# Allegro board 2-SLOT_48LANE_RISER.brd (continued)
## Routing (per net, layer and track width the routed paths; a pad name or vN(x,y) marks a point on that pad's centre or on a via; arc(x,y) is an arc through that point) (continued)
GND_L:
  vias: v2(-18.72,363.74) v2(-18.72,362.74) v2(-18.72,361.74) v2(-18.72,360.74) v2(-18.72,359.74) v2(-18.72,358.74) v2(-18.72,357.74) v2(-18.72,356.74) v2(-18.72,355.74) v2(-18.72,354.74) v2(-18.72,353.74) v2(-18.72,352.74) v2(-18.72,351.74) v2(-18.72,350.74) v2(-18.72,349.74) v2(-18.72,348.74) v2(-18.72,347.74) v2(-18.72,346.74) v2(-18.72,345.74) v2(-18.72,344.74) v2(-18.72,343.74) v2(-18.72,342.74) v2(-18.72,341.74) v2(-18.72,340.74) v2(-18.72,339.74) v2(-18.72,338.74) v2(-18.72,337.74) v2(-18.72,336.74) v2(-18.72,335.74) v2(-18.72,334.74) v2(-18.72,333.74) v2(-18.72,332.74) v2(-18.72,331.74) v2(-18.72,330.74) v2(-18.72,329.74) v2(-18.72,328.74) v2(-18.72,327.74) v2(-18.72,326.74) v2(-18.72,325.74) v2(-18.72,324.74) v2(-18.72,323.74) v2(-18.72,322.74) v2(-18.72,321.74) v2(-18.72,320.74) v2(-18.72,319.74) v2(-18.72,318.74) v2(-18.72,317.74) v2(-18.72,316.74) v2(-18.72,315.74) v2(-18.72,314.74) v2(-18.72,313.74) v2(-18.72,312.74) v2(-18.72,311.74) v2(-18.72,310.74) v2(-18.72,309.74) v2(-18.72,308.74) v2(-18.72,307.74) v2(-18.72,306.74) v2(-18.72,305.74) v2(-18.72,304.74) v2(-18.72,303.74) v2(-18.72,302.74) v2(-18.72,301.74) v2(-18.72,300.74) v2(-18.72,299.74) v2(-18.72,298.74) v2(-18.72,297.74) v2(-18.72,296.74) v2(-18.72,295.74) v2(-18.72,294.74) v2(-18.72,293.74) v2(-18.72,292.74) v2(-18.72,291.74) v2(-18.72,290.74) v2(-18.72,289.74) v2(-18.72,288.74) v2(-18.72,287.74) v2(-18.72,286.74) v2(-18.72,285.74) v2(-18.72,284.74) v2(-18.72,283.74) v2(-18.72,282.74) v2(-18.72,281.74) v2(-18.72,280.74) v2(-18.72,279.74) v2(-18.72,278.74) v2(-18.72,277.74) v2(-18.72,276.74) v2(-18.72,275.74) v2(-18.72,274.74) v2(-18.72,273.74) v2(-18.72,272.74) v2(-18.72,271.74) v2(-18.72,270.74) v2(-18.72,269.74) v2(-18.72,268.74) v2(-18.72,267.74) v2(-18.72,266.74) v2(-18.72,265.74) v2(-18.72,264.74) v2(-18.72,263.74) v2(-18.72,262.74) v2(-18.72,261.74) v2(-18.72,260.74) v2(-18.72,259.74) v2(-18.72,258.74) v2(-18.72,257.74) v2(-18.72,256.74) v2(-18.72,255.74) v2(-18.72,254.74) v2(-18.72,253.74) v2(-18.72,252.74) v2(-18.72,251.74) v2(-18.72,250.74) v2(-18.72,249.74) v2(-18.72,248.74) v2(-18.72,247.74) v2(-18.72,246.74) v2(-18.72,245.74) v2(-18.72,244.74) v2(-18.72,243.74) v2(-18.72,242.74) v2(-18.72,241.74) v2(-18.72,240.74) v2(-18.72,239.74) v2(-18.72,238.74) v2(-18.72,237.74) v2(-18.72,236.74) v2(-18.72,235.74) v2(-18.72,234.74) v2(-18.72,233.74) v2(-18.72,232.74) v2(-18.72,231.74) v2(-18.72,230.74) v2(-18.72,229.74) v2(-18.72,228.74) v2(-18.72,227.74) v2(-18.72,226.74) v2(-18.72,225.74) v2(-18.72,224.74) v2(-18.72,223.74) v2(-18.72,222.74) v2(-18.72,221.74) v2(-18.72,220.74) v2(-18.72,219.74) v2(-18.72,218.74) v2(-18.72,217.74) v2(-18.72,216.74) v2(-18.72,215.74) v2(-18.72,214.74) v2(-18.72,213.74) v2(-18.72,212.74) v2(-18.72,211.74) v2(-18.72,210.74) v2(-18.72,209.74) v2(-18.72,208.74) v2(-18.72,207.74) v2(-18.72,206.74) v2(-18.72,205.74) v2(-18.72,204.74) v2(-18.72,203.74) v2(-18.72,202.74) v2(-18.72,201.74) v2(-18.72,200.74) v2(-18.72,199.74) v2(-18.72,198.74) v2(-18.72,197.74) v2(-18.72,196.74) v2(-18.72,195.74) v2(-18.72,194.74) v2(-18.72,193.74) v2(-18.72,192.74) v2(-18.72,191.74) v2(-18.72,190.74) v2(-18.72,189.74) v2(-18.72,188.74) v2(-18.72,187.74) v2(-18.72,186.74) v2(-18.72,185.74) v2(-18.72,184.74) v2(-18.72,183.74) v2(-18.72,182.74) v2(-18.72,181.74) v2(-18.72,180.74) v2(-18.72,179.74) v2(-18.72,178.74) v2(-18.72,177.74) v2(-18.72,176.74) v2(-18.72,175.74) v2(-18.72,174.74) v2(-18.72,173.74) v2(-18.72,172.74) v2(-18.72,171.74) v2(-18.72,170.74) v2(-18.72,169.74) v2(-18.72,168.74) v2(-18.72,167.74) v2(-18.72,166.74) v2(-18.72,165.74) v2(-18.72,164.74) v2(-18.72,163.74) v2(-18.72,162.74) v2(-18.72,161.74) v2(-18.72,160.74) v2(-18.72,159.74) v2(-18.72,158.74) v2(-18.72,157.74) v2(-18.72,156.74) v2(-18.72,155.74) v2(-18.72,154.74) v2(-18.72,153.74) v2(-18.72,152.74) v2(-18.72,151.74) v2(-18.72,150.74) v2(-18.72,149.74) v2(-18.72,148.74) v2(-18.72,147.74) v2(-18.72,146.74) v2(-18.72,145.74) v2(-18.72,144.74) v2(-18.72,143.74) v2(-18.72,142.74) v2(-18.72,141.74) v2(-18.72,140.74) v2(-18.72,139.74) v2(-18.72,138.74) v2(-18.72,137.74) v2(-18.72,136.74) v2(-18.72,135.74) v2(-18.72,134.74) v2(-18.72,133.74) v2(-18.72,132.74) v2(-18.72,131.74) v2(-18.72,130.74) v2(-18.72,129.74) v2(-18.72,128.74) v2(-18.72,127.74) v2(-18.72,126.74) v2(-18.72,125.74) v2(-18.72,124.74) v2(-18.72,123.74) v2(-18.72,122.74) v2(-18.72,121.74) v2(-18.72,120.74) v2(-18.72,119.74) v2(-18.72,118.74) v2(-18.72,117.74) v2(-18.72,116.74) v2(-18.72,115.74) v2(-18.72,114.74) v2(-18.72,113.74) v2(-18.72,112.74) v2(-18.72,111.74) v2(-18.72,110.74) v2(-18.72,109.74) v2(-18.72,108.74) v2(-18.72,107.74) v2(-18.72,106.74) v2(-18.72,105.74) v2(-18.72,104.74) v2(-18.72,103.74) v2(-18.72,102.74) v2(-18.72,101.74) v2(-18.72,100.74) v2(-18.72,99.74) v2(-18.72,98.74) v2(-18.72,97.74) v2(-18.72,96.74) v2(-18.72,95.74) v2(-18.72,94.74) v2(-18.72,93.74) v2(-18.72,92.74) v2(-18.72,91.74) v2(-18.72,90.74) v2(-18.72,89.74) v2(-18.72,88.74) v2(-18.72,87.74) v2(-18.72,86.74) v2(-18.72,85.74) v2(-18.72,84.74) v2(-18.72,83.74) v2(-18.72,82.74) v2(-18.72,81.74) v2(-18.72,80.74) v2(-18.72,79.74) v2(-18.72,78.74) v2(-18.72,77.74) v2(-18.72,76.74) v2(-18.72,75.74) v2(-18.72,74.74) v2(-18.72,73.74) v2(-18.72,72.74) v2(-18.72,71.74) v2(-18.72,70.74) v2(-18.72,69.74) v2(-18.72,68.74) v2(-18.72,67.74) v2(-18.72,66.74) v2(-18.72,65.74) v2(-18.72,64.74) v2(-18.72,63.74) v2(-18.72,62.74) v2(-18.72,61.74) v2(-18.72,60.74) v2(-18.72,59.74) v2(-18.72,58.74) v2(-18.72,57.74) v2(-18.72,56.74) v2(-18.72,55.74) v2(-18.72,54.74) v2(-18.72,53.74) v2(-18.72,52.74) v2(-18.72,51.74) v2(-18.72,50.74) v2(-18.72,49.74) v2(-18.72,48.74) v2(-18.72,47.74) v2(-18.72,46.74) v2(-18.72,45.74) v2(-18.72,44.74) v2(-18.72,43.74) v2(-18.72,42.74) v2(-18.72,41.74) v2(-18.72,40.74) v2(-18.72,39.74) v2(-18.72,38.74) v2(-18.72,37.74) v2(-18.72,36.74) v2(-18.72,35.74) v2(-18.72,34.74) v2(-18.72,33.74) v2(-18.72,32.74) v2(-18.72,31.74) v2(-18.72,30.74) v2(-18.72,29.74) v2(-18.72,28.74) v2(-18.72,27.74) v2(-18.72,26.74) v2(-18.72,25.74) v2(-18.72,24.74) v2(-18.72,23.74) v2(-18.72,22.74) v2(-18.72,21.74) v2(-18.72,20.74) v2(-18.72,19.74) v2(-18.72,18.74) v2(-18.72,17.74) v2(-18.72,16.74) v2(-18.72,15.74) v2(-18.72,14.74) v2(-18.72,13.74) v2(-18.72,12.74) v2(-18.72,11.74) v2(-18.72,10.74) v2(-18.72,9.74) v2(-18.72,8.74) v2(-18.72,7.74) v2(-18.72,6.74) v2(-18.72,5.74) v2(-18.72,4.74) v2(-18.72,3.74) v2(-18.72,2.74) v2(-18.72,1.74) v2(-18.72,0.74) v2(-18.72,-0.26) v2(-18.72,-1.26) v2(-18.72,-2.26) v2(-18.72,-3.26) v2(-18.72,-4.26) v2(-18.72,-5.26) v2(-18.72,-6.26) v2(-18.72,-7.26) v2(-18.72,-8.26) v2(-17.1,65.8) v2(-17.1,64.8) v2(-17.1,63.8) v2(-17.1,62.8) v2(-17.1,61.8) v2(-17.1,60.8) v2(-17.1,59.8) v2(-17.1,58.8) v2(-17.1,57.8) v2(-17.1,56.8) v2(-17.1,55.8) v2(-17.1,54.8) v2(-17.1,53.8) v2(-17.1,52.8) v2(-17.1,51.8) v2(-17.1,50.8) v2(-16.97,299.48) v2(-16.97,298.48) v2(-16.97,297.48) v2(-16.97,296.48) v2(-16.97,295.48) v2(-16.97,294.48) v2(-16.97,293.48) v2(-16.97,292.48) v2(-16.97,291.48) v2(-16.97,290.48) v2(-16.97,289.48) v2(-16.97,288.48) v2(-16.97,287.48) v2(-16.97,286.48) v2(-16.97,285.48) v2(-16.97,284.48) v2(-16.97,237.38) v2(-16.97,236.38) v2(-16.97,235.38) v2(-16.97,234.38) v2(-16.97,233.38) v2(-16.97,232.38) v2(-16.97,231.38) v2(-16.97,230.38) v2(-16.97,229.38) v2(-16.97,228.38) v2(-16.97,227.38) v2(-16.97,4.21) v2(-16.97,3.21) v2(-16.97,2.21) v2(-16.97,1.21) v2(-16.97,0.21) v2(-16.97,-0.79) v2(-16.97,-1.79) v2(-16.97,-2.79) v2(-16.97,-3.79) v2(-16.97,-4.79) v2(-16.97,-5.79) v2(-16.97,-6.79) v2(-16.97,-7.79) v2(-16.85,180.36) v2(-16.85,179.36) v2(-16.85,178.36) v2(-16.85,177.36) v2(-16.85,176.36) v2(-16.85,175.36) v2(-16.85,174.36) v2(-16.85,173.36) v2(-16.85,172.36) v2(-16.85,171.36) v2(-16.85,170.36) v2(-16.85,122.95) v2(-16.85,121.95) v2(-16.85,120.95) v2(-16.85,119.95) v2(-16.85,118.95) v2(-16.85,117.95) v2(-16.85,116.95) v2(-16.85,115.95) v2(-16.85,114.95) v2(-16.85,113.95) v2(-16.85,112.95) v2(-16.72,363.74) v2(-16.72,362.74) v2(-16.72,361.74) v2(-16.72,360.74) v2(-16.72,359.74) v2(-16.72,358.74) v2(-16.72,357.74) v2(-16.72,356.74) v2(-16.72,355.74) v2(-16.72,354.74) v2(-16.72,353.74) v2(-16.72,352.74) v2(-16.72,351.74) v2(-16.72,350.74) v2(-16.72,349.74) v2(-16.72,348.74) v2(-16.72,347.74) v2(-16.72,346.74) v2(-15.1,65.8) v2(-15.1,64.8) v2(-15.1,63.8) v2(-15.1,62.8) v2(-15.1,61.8) v2(-15.1,60.8) v2(-15.1,59.8) v2(-15.1,58.8) v2(-15.1,57.8) v2(-15.1,56.8) v2(-15.1,55.8) v2(-15.1,54.8) v2(-15.1,53.8) v2(-15.1,52.8) v2(-15.1,51.8) v2(-15.1,50.8) v2(-14.97,299.48) v2(-14.97,298.48) v2(-14.97,297.48) v2(-14.97,296.48) v2(-14.97,295.48) v2(-14.97,294.48) v2(-14.97,293.48) v2(-14.97,292.48) v2(-14.97,291.48) v2(-14.97,290.48) v2(-14.97,289.48) v2(-14.97,288.48) v2(-14.97,287.48) v2(-14.97,286.48) v2(-14.97,285.48) v2(-14.97,284.48) v2(-14.97,237.38) v2(-14.97,236.38) v2(-14.97,235.38) v2(-14.97,234.38) v2(-14.97,233.38) v2(-14.97,232.38) v2(-14.97,231.38) v2(-14.97,230.38) v2(-14.97,229.38) v2(-14.97,228.38) v2(-14.97,227.38) v2(-14.97,4.21) v2(-14.97,3.21) v2(-14.97,2.21) v2(-14.97,1.21) v2(-14.97,0.21) v2(-14.97,-0.79) v2(-14.97,-1.79) v2(-14.97,-2.79) v2(-14.97,-3.79) v2(-14.97,-4.79) v2(-14.97,-5.79) v2(-14.97,-6.79) v2(-14.97,-7.79) v2(-14.85,180.36) v2(-14.85,179.36) v2(-14.85,178.36) v2(-14.85,177.36) v2(-14.85,176.36) v2(-14.85,175.36) v2(-14.85,174.36) v2(-14.85,173.36) v2(-14.85,172.36) v2(-14.85,171.36) v2(-14.85,170.36) v2(-14.85,122.95) v2(-14.85,121.95) v2(-14.85,120.95) v2(-14.85,119.95) v2(-14.85,118.95) v2(-14.85,117.95) v2(-14.85,116.95) v2(-14.85,115.95) v2(-14.85,114.95) v2(-14.85,113.95) v2(-14.85,112.95) v2(-14.72,363.74) v2(-14.72,362.74) v2(-14.72,361.74) v2(-14.72,360.74) v2(-14.72,359.74) v2(-14.72,358.74) v2(-14.72,357.74) v2(-14.72,356.74) v2(-14.72,355.74) v2(-14.72,354.74) v2(-14.72,353.74) v2(-14.72,352.74) v2(-14.72,351.74) v2(-14.72,350.74) v2(-14.72,349.74) v2(-14.72,348.74) v2(-14.72,347.74) v2(-14.72,346.74) v2(-13.1,65.8) v2(-13.1,64.8) v2(-13.1,63.8) v2(-13.1,62.8) v2(-13.1,61.8) v2(-13.1,60.8) v2(-13.1,59.8) v2(-13.1,58.8) v2(-13.1,57.8) v2(-13.1,56.8) v2(-13.1,55.8) v2(-13.1,54.8) v2(-13.1,53.8) v2(-13.1,52.8) v2(-13.1,51.8) v2(-13.1,50.8) v2(-12.97,299.48) v2(-12.97,298.48) v2(-12.97,297.48) v2(-12.97,296.48) v2(-12.97,295.48) v2(-12.97,294.48) v2(-12.97,293.48) v2(-12.97,292.48) v2(-12.97,291.48) v2(-12.97,290.48) v2(-12.97,289.48) v2(-12.97,288.48) v2(-12.97,287.48) v2(-12.97,286.48) v2(-12.97,285.48) v2(-12.97,284.48) v2(-12.97,237.38) v2(-12.97,236.38) v2(-12.97,235.38) v2(-12.97,234.38) v2(-12.97,233.38) v2(-12.97,232.38) v2(-12.97,231.38) v2(-12.97,230.38) v2(-12.97,229.38) v2(-12.97,228.38) v2(-12.97,227.38) v2(-12.97,4.21) v2(-12.97,3.21) v2(-12.97,2.21) v2(-12.97,1.21) v2(-12.97,0.21) v2(-12.97,-0.79) v2(-12.97,-1.79) v2(-12.97,-2.79) v2(-12.97,-3.79) v2(-12.97,-4.79) v2(-12.97,-5.79) v2(-12.97,-6.79) v2(-12.97,-7.79) v2(-12.85,180.36) v2(-12.85,179.36) v2(-12.85,178.36) v2(-12.85,177.36) v2(-12.85,176.36) v2(-12.85,175.36) v2(-12.85,174.36) v2(-12.85,173.36) v2(-12.85,172.36) v2(-12.85,171.36) v2(-12.85,170.36) v2(-12.85,122.95) v2(-12.85,121.95) v2(-12.85,120.95) v2(-12.85,119.95) v2(-12.85,118.95) v2(-12.85,117.95) v2(-12.85,116.95) v2(-12.85,115.95) v2(-12.85,114.95) v2(-12.85,113.95) v2(-12.85,112.95) v2(-12.72,363.74) v2(-12.72,362.74) v2(-12.72,361.74) v2(-12.72,360.74) v2(-12.72,359.74) v2(-12.72,358.74) v2(-12.72,357.74) v2(-12.72,356.74) v2(-12.72,355.74) v2(-12.72,354.74) v2(-12.72,353.74) v2(-12.72,352.74) v2(-12.72,351.74) v2(-12.72,350.74) v2(-12.72,349.74) v2(-12.72,348.74) v2(-12.72,347.74) v2(-12.72,346.74) v2(-11.1,65.8) v2(-11.1,64.8) v2(-11.1,63.8) v2(-11.1,62.8) v2(-11.1,61.8) v2(-11.1,60.8) v2(-11.1,59.8) v2(-11.1,58.8) v2(-11.1,57.8) v2(-11.1,56.8) v2(-11.1,55.8) v2(-11.1,54.8) v2(-11.1,53.8) v2(-11.1,52.8) v2(-11.1,51.8) v2(-11.1,50.8) v2(-10.97,299.48) v2(-10.97,298.48) v2(-10.97,297.48) v2(-10.97,296.48) v2(-10.97,295.48) v2(-10.97,294.48) v2(-10.97,293.48) v2(-10.97,292.48) v2(-10.97,291.48) v2(-10.97,290.48) v2(-10.97,289.48) v2(-10.97,288.48) v2(-10.97,287.48) v2(-10.97,286.48) v2(-10.97,285.48) v2(-10.97,284.48) v2(-10.97,237.38) v2(-10.97,236.38) v2(-10.97,235.38) v2(-10.97,234.38) v2(-10.97,233.38) v2(-10.97,232.38) v2(-10.97,231.38) v2(-10.97,230.38) v2(-10.97,229.38) v2(-10.97,228.38) v2(-10.97,227.38) v2(-10.97,4.21) v2(-10.97,3.21) v2(-10.97,2.21) v2(-10.97,1.21) v2(-10.97,0.21) v2(-10.97,-0.79) v2(-10.97,-1.79) v2(-10.97,-2.79) v2(-10.97,-3.79) v2(-10.97,-4.79) v2(-10.97,-5.79) v2(-10.97,-6.79) v2(-10.97,-7.79) v2(-10.85,180.36) v2(-10.85,179.36) v2(-10.85,178.36) v2(-10.85,177.36) v2(-10.85,176.36) v2(-10.85,175.36) v2(-10.85,174.36) v2(-10.85,173.36) v2(-10.85,172.36) v2(-10.85,171.36) v2(-10.85,170.36) v2(-10.85,122.95) v2(-10.85,121.95) v2(-10.85,120.95) v2(-10.85,119.95) v2(-10.85,118.95) v2(-10.85,117.95) v2(-10.85,116.95) v2(-10.85,115.95) v2(-10.85,114.95) v2(-10.85,113.95) v2(-10.85,112.95) v2(-10.72,363.74) v2(-10.72,362.74) v2(-10.72,361.74) v2(-10.72,360.74) v2(-10.72,359.74) v2(-10.72,358.74) v2(-10.72,357.74) v2(-10.72,356.74) v2(-10.72,355.74) v2(-10.72,354.74) v2(-10.72,353.74) v2(-10.72,352.74) v2(-10.72,351.74) v2(-10.72,350.74) v2(-10.72,349.74) v2(-10.72,348.74) v2(-10.72,347.74) v2(-10.72,346.74) v2(-9.1,65.8) v2(-9.1,64.8) v2(-9.1,63.8) v2(-9.1,62.8) v2(-9.1,61.8) v2(-9.1,60.8) v2(-9.1,59.8) v2(-9.1,58.8) v2(-9.1,57.8) v2(-9.1,56.8) v2(-9.1,55.8) v2(-9.1,54.8) v2(-9.1,53.8) v2(-9.1,52.8) v2(-9.1,51.8) v2(-9.1,50.8) v2(-8.97,299.48) v2(-8.97,298.48) v2(-8.97,297.48) v2(-8.97,296.48) v2(-8.97,295.48) v2(-8.97,294.48) v2(-8.97,293.48) v2(-8.97,292.48) v2(-8.97,291.48) v2(-8.97,290.48) v2(-8.97,289.48) v2(-8.97,288.48) v2(-8.97,287.48) v2(-8.97,286.48) v2(-8.97,285.48) v2(-8.97,284.48) v2(-8.97,237.38) v2(-8.97,236.38) v2(-8.97,235.38) v2(-8.97,234.38) v2(-8.97,233.38) v2(-8.97,232.38) v2(-8.97,231.38) v2(-8.97,230.38) v2(-8.97,229.38) v2(-8.97,228.38) v2(-8.97,227.38) v2(-8.97,4.21) v2(-8.97,3.21) v2(-8.97,2.21) v2(-8.97,1.21) v2(-8.97,0.21) v2(-8.97,-0.79) v2(-8.97,-1.79) v2(-8.97,-2.79) v2(-8.97,-3.79) v2(-8.97,-4.79) v2(-8.97,-5.79) v2(-8.97,-6.79) v2(-8.97,-7.79) v2(-8.85,180.36) v2(-8.85,179.36) v2(-8.85,178.36) v2(-8.85,177.36) v2(-8.85,176.36) v2(-8.85,175.36) v2(-8.85,174.36) v2(-8.85,173.36) v2(-8.85,172.36) v2(-8.85,171.36) v2(-8.85,170.36) v2(-8.85,122.95) v2(-8.85,121.95) v2(-8.85,120.95) v2(-8.85,119.95) v2(-8.85,118.95) v2(-8.85,117.95) v2(-8.85,116.95) v2(-8.85,115.95) v2(-8.85,114.95) v2(-8.85,113.95) v2(-8.85,112.95) v2(-8.72,363.74) v2(-8.72,362.74) v2(-8.72,361.74) v2(-8.72,360.74) v2(-8.72,359.74) v2(-8.72,358.74) v2(-8.72,357.74) v2(-8.72,356.74) v2(-8.72,355.74) v2(-8.72,354.74) v2(-8.72,353.74) v2(-8.72,352.74) v2(-8.72,351.74) v2(-8.72,350.74) v2(-8.72,349.74) v2(-8.72,348.74) v2(-8.72,347.74) v2(-8.72,346.74) v2(-8.18,164.21) v2(-8.18,129.79) v2(-7.42,164.21) v2(-7.42,129.79) v2(-7.1,65.8) v2(-7.1,64.8) v2(-7.1,63.8) v2(-7.1,62.8) v2(-7.1,61.8) v2(-7.1,60.8) v2(-7.1,59.8) v2(-7.1,58.8) v2(-7.1,57.8) v2(-7.1,56.8) v2(-7.1,55.8) v2(-7.1,54.8) v2(-7.1,53.8) v2(-7.1,52.8) v2(-7.1,51.8) v2(-7.1,50.8) v2(-6.97,299.48) v2(-6.97,298.48) v2(-6.97,297.48) v2(-6.97,296.48) v2(-6.97,295.48) v2(-6.97,294.48) v2(-6.97,293.48) v2(-6.97,292.48) v2(-6.97,291.48) v2(-6.97,290.48) v2(-6.97,289.48) v2(-6.97,288.48) v2(-6.97,287.48) v2(-6.97,286.48) v2(-6.97,285.48) v2(-6.97,284.48) v2(-6.97,237.38) v2(-6.97,236.38) v2(-6.97,235.38) v2(-6.97,234.38) v2(-6.97,233.38) v2(-6.97,232.38) v2(-6.97,231.38) v2(-6.97,230.38) v2(-6.97,229.38) v2(-6.97,228.38) v2(-6.97,227.38) v2(-6.97,4.21) v2(-6.97,3.21) v2(-6.97,2.21) v2(-6.97,1.21) v2(-6.97,0.21) v2(-6.97,-0.79) v2(-6.97,-1.79) v2(-6.97,-2.79) v2(-6.97,-3.79) v2(-6.97,-4.79) v2(-6.97,-5.79) v2(-6.97,-6.79) v2(-6.97,-7.79) v2(-6.85,180.36) v2(-6.85,179.36) v2(-6.85,178.36) v2(-6.85,177.36) v2(-6.85,176.36) v2(-6.85,175.36) v2(-6.85,174.36) v2(-6.85,173.36) v2(-6.85,172.36) v2(-6.85,171.36) v2(-6.85,170.36) v2(-6.85,122.95) v2(-6.85,121.95) v2(-6.85,120.95) v2(-6.85,119.95) v2(-6.85,118.95) v2(-6.85,117.95) v2(-6.85,116.95) v2(-6.85,115.95) v2(-6.85,114.95) v2(-6.85,113.95) v2(-6.85,112.95) v2(-6.72,363.74) v2(-6.72,362.74) v2(-6.72,361.74) v2(-6.72,358.74) v2(-6.72,357.74) v2(-6.72,356.74) v2(-6.72,355.74) v2(-6.72,354.74) v2(-6.72,353.74) v2(-6.72,352.74) v2(-6.72,351.74) v2(-6.72,348.74) v2(-6.72,347.74) v2(-6.72,346.74) v2(-4.96,65.8) v2(-4.96,64.8) v2(-4.96,63.8) v2(-4.96,62.8) v2(-4.96,61.8) v2(-4.96,60.8) v2(-4.96,59.8) v2(-4.96,58.8) v2(-4.96,57.8) v2(-4.96,56.8) v2(-4.96,55.8) v2(-4.96,54.8) v2(-4.96,53.8) v2(-4.96,52.8) v2(-4.96,51.8) v2(-4.96,50.8) v2(-4.83,299.48) v2(-4.83,298.48) v2(-4.83,297.48) v2(-4.83,296.48) v2(-4.83,295.48) v2(-4.83,294.48) v2(-4.83,293.48) v2(-4.83,292.48) v2(-4.83,291.48) v2(-4.83,290.48) v2(-4.83,289.48) v2(-4.83,288.48) v2(-4.83,287.48) v2(-4.83,286.48) v2(-4.83,285.48) v2(-4.83,284.48) v2(-4.83,237.38) v2(-4.83,236.38) v2(-4.83,235.38) v2(-4.83,234.38) v2(-4.83,233.38) v2(-4.83,232.38) v2(-4.83,231.38) v2(-4.83,230.38) v2(-4.83,229.38) v2(-4.83,228.38) v2(-4.83,227.38) v2(-4.83,4.21) v2(-4.83,3.21) v2(-4.83,-1.79) v2(-4.83,-6.79) v2(-4.83,-7.79) v2(-4.7,180.36) v2(-4.7,179.36) v2(-4.7,178.36) v2(-4.7,177.36) v2(-4.7,176.36) v2(-4.7,175.36) v2(-4.7,174.36) v2(-4.7,173.36) v2(-4.7,172.36) v2(-4.7,171.36) v2(-4.7,170.36) v2(-4.7,122.95) v2(-4.7,121.95) v2(-4.7,120.95) v2(-4.7,119.95) v2(-4.7,118.95) v2(-4.7,117.95) v2(-4.7,116.95) v2(-4.7,115.95) v2(-4.7,114.95) v2(-4.7,113.95) v2(-4.7,112.95) v2(-4.58,363.74) v2(-4.58,362.74) v2(-4.58,357.74) v2(-4.58,356.74) v2(-4.58,355.74) v2(-4.58,354.74) v2(-4.58,353.74) v2(-4.58,352.74) v2(-4.58,347.74) v2(-4.58,346.74) v2(-2.97,363.74) v2(-2.97,362.74) v2(-2.97,361.74) v2(-2.97,360.74) v2(-2.97,359.74) v2(-2.97,358.74) v2(-2.97,357.74) v2(-2.97,356.74) v2(-2.97,355.74) v2(-2.97,354.74) v2(-2.97,353.74) v2(-2.97,352.74) v2(-2.97,351.74) v2(-2.97,350.74) v2(-2.97,349.74) v2(-2.97,348.74) v2(-2.97,347.74) v2(-2.97,346.74) v2(-2.97,345.74) v2(-2.97,344.74) v2(-2.97,343.74) v2(-2.97,342.74) v2(-2.97,341.74) v2(-2.97,340.74) v2(-2.97,339.74) v2(-2.97,338.74) v2(-2.97,337.74) v2(-2.97,336.74) v2(-2.97,335.74) v2(-2.97,334.74) v2(-2.97,333.74) v2(-2.97,332.74) v2(-2.97,331.74) v2(-2.97,330.74) v2(-2.97,329.74) v2(-2.97,328.74) v2(-2.97,327.74) v2(-2.97,326.74) v2(-2.97,325.74) v2(-2.97,324.74) v2(-2.97,323.74) v2(-2.97,322.74) v2(-2.97,321.74) v2(-2.97,320.74) v2(-2.97,319.74) v2(-2.97,318.74) v2(-2.97,317.74) v2(-2.97,316.74) v2(-2.97,315.74) v2(-2.97,314.74) v2(-2.97,313.74) v2(-2.97,312.74) v2(-2.97,311.74) v2(-2.97,310.74) v2(-2.97,309.74) v2(-2.97,308.74) v2(-2.97,307.74) v2(-2.97,306.74) v2(-2.97,305.74) v2(-2.97,304.74) v2(-2.97,303.74) v2(-2.97,302.74) v2(-2.97,301.74) v2(-2.97,300.74) v2(-2.97,299.74) v2(-2.97,298.74) v2(-2.97,297.74) v2(-2.97,296.74) v2(-2.97,295.74) v2(-2.97,294.74) v2(-2.97,293.74) v2(-2.97,292.74) v2(-2.97,291.74) v2(-2.97,290.74) v2(-2.97,289.74) v2(-2.97,288.74) v2(-2.97,287.74) v2(-2.97,286.74) v2(-2.97,285.74) v2(-2.97,284.74) v2(-2.97,283.74) v2(-2.97,282.74) v2(-2.97,281.74) v2(-2.97,280.74) v2(-2.97,279.74) v2(-2.97,278.74) v2(-2.97,277.74) v2(-2.97,276.74) v2(-2.97,275.74) v2(-2.97,274.74) v2(-2.97,273.74) v2(-2.97,272.74) v2(-2.97,271.74) v2(-2.97,270.74) v2(-2.97,269.74) v2(-2.97,268.74) v2(-2.97,267.74) v2(-2.97,266.74) v2(-2.97,265.74) v2(-2.97,264.74) v2(-2.97,263.74) v2(-2.97,262.74) v2(-2.97,261.74) v2(-2.97,260.74) v2(-2.97,259.74) v2(-2.97,258.74) v2(-2.97,257.74) v2(-2.97,256.74) v2(-2.97,255.74) v2(-2.97,254.74) v2(-2.97,253.74) v2(-2.97,252.74) v2(-2.97,251.74) v2(-2.97,250.74) v2(-2.97,249.74) v2(-2.97,248.74) v2(-2.97,247.74) v2(-2.97,246.74) v2(-2.97,245.74) v2(-2.97,244.74) v2(-2.97,243.74) v2(-2.97,242.74) v2(-2.97,241.74) v2(-2.97,240.74) v2(-2.97,239.74) v2(-2.97,238.74) v2(-2.97,237.74) v2(-2.97,236.74) v2(-2.97,235.74) v2(-2.97,234.74) v2(-2.97,233.74) v2(-2.97,232.74) v2(-2.97,231.74) v2(-2.97,230.74) v2(-2.97,229.74) v2(-2.97,228.74) v2(-2.97,227.74) v2(-2.97,226.74) v2(-2.97,225.74) v2(-2.97,224.74) v2(-2.97,223.74) v2(-2.97,222.74) v2(-2.97,221.74) v2(-2.97,220.74) v2(-2.97,219.74) v2(-2.97,218.74) v2(-2.97,217.74) v2(-2.97,216.74) v2(-2.97,215.74) v2(-2.97,214.74) v2(-2.97,213.74) v2(-2.97,212.74) v2(-2.97,211.74) v2(-2.97,210.74) v2(-2.97,209.74) v2(-2.97,208.74) v2(-2.97,207.74) v2(-2.97,206.74) v2(-2.97,205.74) v2(-2.97,204.74) v2(-2.97,203.74) v2(-2.97,202.74) v2(-2.97,201.74) v2(-2.97,200.74) v2(-2.97,199.74) v2(-2.97,198.74) v2(-2.97,197.74) v2(-2.97,196.74) v2(-2.97,195.74) v2(-2.97,194.74) v2(-2.97,193.74) v2(-2.97,192.74) v2(-2.97,191.74) v2(-2.97,190.74) v2(-2.97,189.74) v2(-2.97,188.74) v2(-2.97,187.74) v2(-2.97,186.74) v2(-2.97,185.74) v2(-2.97,184.74) v2(-2.97,183.74) v2(-2.97,182.74) v2(-2.97,181.74) v2(-2.97,180.74) v2(-2.97,179.74) v2(-2.97,178.74) v2(-2.97,177.74) v2(-2.97,176.74) v2(-2.97,175.74) v2(-2.97,174.74) v2(-2.97,173.74) v2(-2.97,172.74) v2(-2.97,171.74) v2(-2.97,170.74) v2(-2.97,169.74) v2(-2.97,168.74) v2(-2.97,167.74) v2(-2.97,166.74) v2(-2.97,165.74) v2(-2.97,164.74) v2(-2.97,163.74) v2(-2.97,162.74) v2(-2.97,161.74) v2(-2.97,160.74) v2(-2.97,159.74) v2(-2.97,158.74) v2(-2.97,157.74) v2(-2.97,156.74) v2(-2.97,155.74) v2(-2.97,154.74) v2(-2.97,153.74) v2(-2.97,152.74) v2(-2.97,151.74) v2(-2.97,150.74) v2(-2.97,149.74) v2(-2.97,148.74) v2(-2.97,147.74) v2(-2.97,146.74) v2(-2.97,145.74) v2(-2.97,144.74) v2(-2.97,143.74) v2(-2.97,142.74) v2(-2.97,141.74) v2(-2.97,140.74) v2(-2.97,139.74) v2(-2.97,138.74) v2(-2.97,137.74) v2(-2.97,136.74) v2(-2.97,135.74) v2(-2.97,134.74) v2(-2.97,133.74) v2(-2.97,132.74) v2(-2.97,131.74) v2(-2.97,130.74) v2(-2.97,129.74) v2(-2.97,128.74) v2(-2.97,127.74) v2(-2.97,126.74) v2(-2.97,125.74) v2(-2.97,124.74) v2(-2.97,123.74) v2(-2.97,122.74) v2(-2.97,121.74) v2(-2.97,120.74) v2(-2.97,119.74) v2(-2.97,118.74) v2(-2.97,117.74) v2(-2.97,116.74) v2(-2.97,115.74) v2(-2.97,114.74) v2(-2.97,113.74) v2(-2.97,112.74) v2(-2.97,111.74) v2(-2.97,110.74) v2(-2.97,109.74) v2(-2.97,108.74) v2(-2.97,107.74) v2(-2.97,106.74) v2(-2.97,105.74) v2(-2.97,104.74) v2(-2.97,103.74) v2(-2.97,102.74) v2(-2.97,101.74) v2(-2.97,100.74) v2(-2.97,99.74) v2(-2.97,98.74) v2(-2.97,97.74) v2(-2.97,96.74) v2(-2.97,95.74) v2(-2.97,94.74) v2(-2.97,93.74) v2(-2.97,92.74) v2(-2.97,91.74) v2(-2.97,90.74) v2(-2.97,89.74) v2(-2.97,88.74) v2(-2.97,87.74) v2(-2.97,86.74) v2(-2.97,85.74) v2(-2.97,84.74) v2(-2.97,83.74) v2(-2.97,82.74) v2(-2.97,81.74) v2(-2.97,80.74) v2(-2.97,79.74) v2(-2.97,78.74) v2(-2.97,77.74) v2(-2.97,76.74) v2(-2.97,75.74) v2(-2.97,74.74) v2(-2.97,73.74) v2(-2.97,72.74) v2(-2.97,71.74) v2(-2.97,70.74) v2(-2.97,69.74) v2(-2.97,68.74) v2(-2.97,67.74) v2(-2.97,66.74) v2(-2.97,65.74) v2(-2.97,64.74) v2(-2.97,63.74) v2(-2.97,62.74) v2(-2.97,61.74) v2(-2.97,60.74) v2(-2.97,59.74) v2(-2.97,58.74) v2(-2.97,57.74) v2(-2.97,56.74) v2(-2.97,55.74) v2(-2.97,54.74) v2(-2.97,53.74) v2(-2.97,52.74) v2(-2.97,51.74) v2(-2.97,50.74) v2(-2.97,49.74) v2(-2.97,48.74) v2(-2.97,47.74) v2(-2.97,46.74) v2(-2.97,45.74) v2(-2.97,44.74) v2(-2.97,43.74) v2(-2.97,42.74) v2(-2.97,41.74) v2(-2.97,40.74) v2(-2.97,39.74) v2(-2.97,38.74) v2(-2.97,37.74) v2(-2.97,36.74) v2(-2.97,35.74) v2(-2.97,34.74) v2(-2.97,33.74) v2(-2.97,32.74) v2(-2.97,31.74) v2(-2.97,30.74) v2(-2.97,29.74) v2(-2.97,28.74) v2(-2.97,27.74) v2(-2.97,26.74) v2(-2.97,25.74) v2(-2.97,24.74) v2(-2.97,23.74) v2(-2.97,22.74) v2(-2.97,21.74) v2(-2.97,20.74) v2(-2.97,19.74) v2(-2.97,18.74) v2(-2.97,17.74) v2(-2.97,16.74) v2(-2.97,15.74) v2(-2.97,14.74) v2(-2.97,13.74) v2(-2.97,12.74) v2(-2.97,11.74) v2(-2.97,10.74) v2(-2.97,9.74) v2(-2.97,8.74) v2(-2.97,7.74) v2(-2.97,6.74) v2(-2.97,5.74) v2(-2.97,4.74) v2(-2.97,3.74) v2(-2.97,2.74) v2(-2.97,1.74) v2(-2.97,0.74) v2(-2.97,-0.26) v2(-2.97,-1.26) v2(-2.97,-2.26) v2(-2.97,-3.26) v2(-2.97,-4.26) v2(-2.97,-5.26) v2(-2.97,-6.26) v2(-2.97,-7.26) v2(-2.97,-8.26)
P0V9: length 320.4
  TOP w0.203: C398.1 v5(128.89,89.16) ; C438.1 v5(132.09,89.96) C16.1 ; C394.1 v5(132.09,85.96) ; C442.1 v5(128.09,84.36) ; C277.1 v5(132.89,83.56) ; C426.1 v5(129.69,85.96) ; C273.1 v5(129.69,82.76) ; C22.1 v5(129.69,89.96) ; C434.1 v5(132.89,87.56) ; C402.1 v5(130.49,87.56) C430.1 ; C279.1 v5(128.89,85.16) ; C275.1 v5(132.09,88.36) C283.1 ; C290.1 v5(130.49,83.56) ; C271.1 v5(129.69,84.36) ; C20.1 v5(132.89,89.16) ; C287.1 v5(132.09,82.76) ; C9.1 v5(128.09,89.96) ; C294.1 v5(130.49,85.16) ; C414.1 v5(133.69,85.96) ; C281.1 v5(128.89,83.56) ; C269.1 v5(129.69,88.36) ; C422.1 v5(128.89,87.56) ; C418.1 v5(132.89,85.16) ; C18.1 v5(133.69,84.36) ; C297.1 v5(132.09,84.36) ; C410.1 v5(130.49,89.16)
  TOP w0.254: v4(85.17,61.19) 84,60.02 84,57.05 83.29,56.34 68.81,56.34 66.94,54.46 PR430.2 ; v2(84.21,65.59) 84.21,65.11 PR434.2 ; 128.4,82.97 v5(128.09,82.76)
  TOP w0.381: C145.1 v7(140.4,75.85) ; C147.1 v7(141.95,75.32) ; R148.1 v2(258.19,29.92)
  IN1 w0.254: v5(132.09,82.76) 131.73,82.76 131.47,82.5 131.47,78.49 128.04,75.06 122.89,75.06 122.51,75.44 118.57,75.44 117.43,74.3 117.43,72.26 113.23,68.07 101.86,68.07 100.41,66.62 84.33,66.62 84.08,66.37 84.08,65.72 v2(84.21,65.59)
  IN1 w0.762: v2(94.31,58.17) 94.31,48.13 102.41,40.03 123.04,40.03 130.51,47.5 176.05,47.5 197.16,26.39 259.13,26.39 259.67,26.93 259.67,29.16 258.91,29.92 v2(258.19,29.92)
  BOTTOM w0.254: U1.M16 v5(132.09,89.96) ; U1.M10 v5(132.09,84.36) ; U1.T10 v5(128.09,84.36) ; U1.R15 v5(128.89,89.16) ; U1.N13 v5(130.49,87.56) ; U1.K12 v5(133.69,85.96) ; v5(129.69,82.76) U1.P8 ; U1.N9 v5(130.49,83.56) ; U1.M14 v5(132.09,88.36) U1.L15 v5(132.89,89.16) U1.K16 ; U1.T16 v5(128.09,89.96) ; U1.P16 v5(129.69,89.96) ; U1.P10 v5(129.69,84.36) ; U1.K10 v5(133.69,84.36) ; U1.L9 v5(132.89,83.56) U1.K8 ; U1.N11 v5(130.49,85.16) ; U1.T14 v5(128.89,87.56) U1.R13 U1.T12 ; U1.R11 v5(128.89,85.16) ; v5(128.09,82.76) U1.T8 v5(128.89,83.56) U1.R9 ; U1.L13 v5(132.89,87.56) U1.K14 ; U1.M12 v5(132.09,85.96) ; U1.N15 v5(130.49,89.16) ; U1.P12 v5(129.69,85.96) ; U1.L11 v5(132.89,85.16) ; U1.M8 v5(132.09,82.76) ; U1.P14 v5(129.69,88.36)
  BOTTOM w0.381: C176.1 v2(101.42,86.67) ; C174.1 v2(101.19,81.81)
  vias: v2(87.96,61.98) v2(87.96,60.71) v2(87.96,59.44) v2(87.96,58.17) v2(89.23,61.98) v2(89.23,60.71) v2(89.23,59.44) v2(89.23,58.17) v2(90.5,61.98) v2(90.5,60.71) v2(90.5,59.44) v2(90.5,58.17) v2(91.77,61.98) v2(91.77,60.71) v2(91.77,59.44) v2(91.77,58.17) v2(93.04,61.98) v2(93.04,60.71) v2(93.04,59.44) v2(93.04,58.17) v2(94.31,61.98) v2(94.31,60.71) v2(94.31,59.44) v6(92.13,63.68)
P0V9_A: length 47.5
  TOP w0.203: v5(127.29,85.16) C6.1 ; C161.1 v5(135.29,89.96) ; C7.1 v5(127.29,89.16) ; v5(127.29,89.96) C17.1 ; C164.1 v5(129.69,81.96) ; C4.1 v5(126.49,86.76) ; C19.1 v5(135.29,82.76) ; C144.1 v5(133.69,89.96) ; v5(134.49,83.56) C10.1 ; C151.1 v5(135.29,90.76) ; C15.1 v5(127.29,83.56) ; C14.1 v5(134.49,85.16) ; C141.1 v5(135.29,85.96) ; C150.1 v5(127.29,82.76) ; C148.1 v5(135.29,81.16) ; C162.1 v5(127.29,91.56) ; C2.1 v5(126.49,89.16) ; C21.1 v5(135.29,83.56) ; C146.1 v5(134.49,89.16) ; C142.1 v5(133.69,81.16) ; C5.1 v5(128.09,91.56) ; C163.1 v5(132.09,81.96)
  TOP w0.254: v5(132.09,90.76) 132.05,90.8 C406.1 ; C390.1 127.28,88.38 127.28,88.36 v5(127.29,88.36) ; C194.1 v5(128.89,81.96) ; C143.1 v5(134.49,87.56)
  TOP w0.381: v2(92.97,75.18) 92.45,75.7 C177.1 ; C175.1 92.45,77.72 v2(92.99,78.26) ; C3.1 135.32,99.39 v2(135.23,98.88) ; C160.1 v2(140.03,98.93) ; C8.1 v2(141.43,98.93) ; C12.1 v2(143.72,98.87)
  BOTTOM w0.254: U1.K17 133.29,90.36 v5(133.69,89.96) 134.09,89.56 U1.J16 ; U1.R6 v5(128.89,81.16) ; v5(127.29,83.56) 127.69,83.16 U1.U8 v5(127.29,82.76) ; U1.J7 v5(133.69,82.76) 134.09,83.16 U1.J8 134.09,83.16 v5(134.49,83.56) ; U1.J18 134.09,91.16 v5(133.69,91.56) U1.K18 v5(132.89,91.56) U1.L18 v5(132.09,90.76) U1.M17 U1.N17 ; U1.H12 v5(135.29,85.96) ; U1.R7 v5(129.69,81.96) ; U1.J15 v5(134.49,89.16) ; v5(134.49,89.16) 134.89,88.76 U1.H15 ; v5(134.49,89.16) U1.H16 v5(135.29,89.96) ; U1.H17 v5(135.29,90.76) ; U1.N7 U1.M7 ; U1.K6 v5(133.69,81.16) ; U1.J9 v5(134.49,83.56) ; v5(134.49,83.56) 134.89,83.96 U1.H9 v5(135.29,83.56) U1.H8 v5(135.29,82.76) 134.89,82.36 U1.H7 v5(135.29,81.96) 134.89,81.56 U1.H6 v5(135.29,81.16) ; U1.V12 v5(126.49,86.76) ; U1.J11 v5(134.49,85.16) ; U1.J13 v5(134.49,87.56) ; U1.T6 v5(128.89,81.96) ; U1.T18 v5(128.09,91.56) U1.U18 v5(127.29,91.56)
  BOTTOM w0.279: U1.U11 v5(127.29,85.16) ; U1.M7 v5(132.09,81.96) ; U1.U9 v5(127.29,83.56)
  BOTTOM w0.356: U1.U14 v5(127.29,88.36)
  BOTTOM w0.381: v5(127.29,89.96) U1.V16 v5(126.49,89.16) ; v5(127.29,89.96) U1.U17 ; v5(127.29,89.96) U1.U16 v5(127.29,89.16) ; v5(127.29,88.36) U1.V15 v5(127.29,89.16) ; U1.U15 v5(127.29,89.16)
  vias: v2(93.8,76.83) v2(93.93,77.72) v2(93.93,72.9) v2(94.82,76.83) v2(94.95,77.72) v2(94.95,72.9) v2(95.71,76.83) v2(95.84,72.9) v2(95.96,77.72) v6(142.06,97.28)
P0V9_AGND: length 4
  BOTTOM w0.305: v2(68.84,45.71) PU23.4 67.49,45.72 66.77,45.72 v4(66.62,45.87) 64.98,45.87 PR423.2
P0V9_COMP: length 6.6
  BOTTOM w0.254: PU23.3 67.11,45.06 66.88,45.29 66.23,45.29 PC589.1 64.41,44.98 64.15,45.23 64.15,46.23 v6(63.73,46.65) 63.49,46.4 PR427.1
P0V9_COMP_RC: length 2.6
  BOTTOM w0.254: PC591.1 63.91,44.18 v6(62.93,44.18) 62.69,44.42 PR427.2
P0V9_EN: length 7.2
  TOP w0.254: PR418.2 65.92,40.14 66.17,39.89 66.53,39.89 v1(66.72,40.08) 66.72,40.92 v2(66.74,40.94)
  BOTTOM w0.203: PU23.15 68.98,42.74 68.65,42.41 67.69,42.41 66.82,41.54 66.82,41.01 v2(66.74,40.94)
  BOTTOM w0.254: PC580.1 66.14,40.33 v2(66.74,40.94)
P0V9_FB: length 7.8
  TOP w0.254: PR429.2 67.64,44.6 66.8,43.76 v4(66.63,43.76)
  BOTTOM w0.254: PC589.2 66.09,44.18 66.36,43.91 66.47,43.91 v4(66.63,43.76) PU23.1 ; PC589.2 65.68,44.41 PC591.2 ; PC589.2 PR431.1 64.7,43.22 64.47,42.99 PR432.1
P0V9_FB_RC: length 2.8
  BOTTOM w0.254: PC597.1 65.03,41.97 v6(65.76,41.23) 65.92,41.39 PR431.2
P0V9_PG: length 324.4
  TOP w0.114: Q7.G 302.88,22.01 v2(300.79,24.1) ; R297.1 294.08,50.89 294.08,45.09 295.04,44.13 295.05,44.13 296.42,42.76 298.11,42.76 298.81,42.06 v2(298.81,41.43)
  IN2 w0.147: v2(59.67,47.6) 59.67,43.28 67.08,35.87 100.12,35.87 103.07,38.82 103.07,43.18 105.05,45.15 108.65,45.15 109.35,44.45 130.38,44.45 133.05,47.12 174.65,47.12 200.95,20.82 235.03,20.82 246.76,9.09 269.98,9.09 276.4,15.52 284.94,15.52 292.13,22.71 299.39,22.71 v2(300.79,24.1) 300.79,28.24 299.68,29.35 299.68,31.61 298.27,33.02 298.27,40.89 v2(298.81,41.43)
  BOTTOM w0.114: v2(59.67,47.6) 61.16,49.1 65.15,49.1 65.49,49.44 PR420.2
  BOTTOM w0.254: PR420.2 65.83,49.74 67.18,48.39 67.18,47.78 67.31,47.66 PU23.7
P0V9_PG_LED_H: length 2.2
  TOP w0.114: D1.A 305.64,25.78 v2(305.26,25.4) 304.64,25.4 R110.1
P0V9_PG_LED_N: length 4.6
  TOP w0.114: Q7.D 305.6,23.62 v2(306.91,23.62) 307.27,23.98 R109.2 307.27,25.15 307.66,25.53 D1.C
P0V9_RT: length 2.8
  BOTTOM w0.254: PR423.1 65.05,46.83 66.15,46.83 v6(66.17,46.81) 66.58,46.81 67.03,46.36 PU23.5
P0V9_SENSE_R_N: length 53.7
  TOP w0.254: PR435.1 83.31,64.12 83.62,63.81 83.62,63.42 v2(83.47,63.27) 83.59,63.15 83.59,62.44 83.28,62.13 69.55,62.13 61.57,54.15 61.57,41.71 62.82,40.46 63.62,40.46 64.21,41.05 64.21,41.92 v1(64.81,42.53) 64.85,42.49 66.47,42.49 67.5,43.53 67.81,43.53 68.55,44.26 PR429.1 68.55,44.76 68.23,45.08 68.23,45.82 68.55,46.15 PR504.2 68.6,46.43 PR428.1
  BOTTOM w0.254: v2(83.47,63.27) 83.52,63.22 83.52,62.74 83.28,62.5 PR505.1
P0V9_SENSE_R_P: length 44.9
  TOP w0.254: v2(63.22,41.07) 62.79,41.07 61.95,41.91 61.95,53.99 69.7,61.75 83.44,61.75 83.97,62.28 83.97,63.04 v2(84.2,63.27) 84,63.47 84,63.83 84.29,64.12 PR434.1
  BOTTOM w0.254: PR433.1 84.39,62.5 84.15,62.74 84.15,63.22 v2(84.2,63.27) ; PR432.2 63.22,41.94 v2(63.22,41.07) 64.44,41.07 PC597.2
P0V9_VCC: length 9.8
  IN2 w0.254: v4(65.87,48.65) 66.62,47.89 68.88,47.89 69.33,48.35 69.33,49.09 v2(69.52,49.27)
  BOTTOM w0.254: v4(65.87,48.65) 66.06,48.45 66.06,48.11 67.17,47.01 PU23.6 ; v2(69.52,49.27) 69.63,49.16 PU23.10
  BOTTOM w0.381: PC581.2 69.52,49.96 v2(69.52,49.27)
P0V9_VIN: length 4.1
  TOP w0.508: PR426.2 68.82,50.14 v2(68.82,49.24)
  BOTTOM w0.254: v2(68.82,49.24) 68.98,49.08 PU23.9
  BOTTOM w0.381: v2(68.82,49.24) 68.52,49.54 PC583.1
P0V9_VREF: length 2.2
  TOP w0.254: PC582.1 66.37,44.84 66.57,44.64 v7(66.66,44.64)
  BOTTOM w0.254: PU23.2 66.89,44.41 v7(66.66,44.64)
P0V9_VSNS: length 4.8
  TOP w0.254: PR428.2 68.6,48.33 67.9,49.03 v2(67.34,49.03) 67.45,49.14 67.45,49.51 67.74,49.8 PR430.1
  BOTTOM w0.254: PU23.8 68.33,48.62 67.91,49.04 67.35,49.04 v2(67.34,49.03)
P1V8: length 271.1
  TOP w0.203: 134.28,91.07 v5(134.49,90.76) ; C53.1 v5(130.49,81.16) ; C133.1 v5(133.69,81.96) ; C131.1 130.25,91.8 v5(130.49,91.56) ; C135.1 v5(128.09,81.96) ; C139.1 v5(128.09,90.76)
  TOP w0.254: C129.1 127.33,86 v5(127.29,85.96) ; R57.1 130.5,91.55 v5(130.49,91.56) ; C181.1 v5(134.49,85.96)
  TOP w0.356: R60.1 R62.1
  TOP w0.381: R53.1 131.9,74.04 v2(131.65,73.79) ; R351.1 166.45,112.52 165.3,111.38 163.27,111.38 160.61,114.05 159.9,114.05 U11.5 158.71,114.03 C155.1 158.67,114.83 158.35,115.15 157.42,115.15 ; R54.1 R50.1 127.71,74.12 128.09,73.74 v2(128.47,73.74) ; R55.1 v2(100.41,98.81) R56.1 ; R64.1 v2(110.57,100.35) ; R69.1 v2(108.79,98.93) R49.1 ; v2(124.11,73.53) 124.66,74.09 R72.1 R74.1 ; R121.1 R128.1 133.05,99.14 v2(132.64,98.73) ; R51.1 v2(105.74,100.97) ; R94.1 134.19,74.04 v2(134.57,73.66) ; v2(98.5,100.08) 98.78,100.35 R113.1 ; U12.1 v2(106.34,49.74) ; R70.1 v2(125.81,104.14) R117.1 ; R60.1 146.51,85.22 v2(146.76,84.96) ; R52.1 v2(101.42,98.81) ; v2(257.38,27.81) 257.58,27.81 258.52,26.87 R146.1 ; R93.1 v2(138.25,73.69) ; R46.1 v2(139.27,73.69) ; v2(130,73.79) 129.87,73.91 R47.1 ; U6.8 132.95,109.22 C1.1 131.8,109.96 v2(131.78,109.98) 131.63,110.13 R129.1 ; R115.1 v2(122.51,106.17) ; R48.1 v2(126.82,106.17) ; R111.1 v2(137.24,73.69) ; C127.1 v2(121.49,106.17)
  TOP w0.457: R120.1 136.22,99.16 v2(135.99,98.93) ; v2(140.18,102.49) 140.18,103.42 C48.1 139.3,103.34 v2(139.3,102.49)
  TOP w0.508: v2(137.56,115.15) 157.42,115.15
  IN1 w0.762: 103.25,49.96 102.34,49.05 102.34,42.75 103.68,41.4 122.43,41.4 130.46,49.43 176.89,49.43 198.6,27.71 257.28,27.71 v2(257.38,27.81)
  IN2 w0.508: v2(125.55,106.55) 127.08,108.08 130.89,108.08 131.78,108.97 v2(131.78,109.98) 131.78,112.9 133.57,114.7 137.1,114.7 v2(137.56,115.15)
  BOTTOM w0.254: U1.J17 v5(134.49,90.76) ; U1.J12 v5(134.49,85.96) ; U1.T7 v5(128.09,81.96) ; U1.N6 v5(130.49,81.16) ; U1.K7 v5(133.69,81.96) ; U1.T17 v5(128.09,90.76) ; U1.N18 v5(130.49,91.56)
  BOTTOM w0.279: U1.U12 v5(127.29,85.96)
  BOTTOM w0.381: v2(106.34,49.74) 106.38,49.7 C451.1 ; R277.1 R278.1 103.52,48.79 v2(103.45,48.86)
  vias: v1(99.01,105.66) v2(96.5,106.68) v2(96.5,105.92) v2(97.39,106.68) v2(97.39,105.92) v2(98.27,106.68) v2(98.27,105.92) v2(98.27,105.16) v2(115.44,105.03) v2(115.44,104.14) v2(115.44,103.12) v2(116.33,104.14) v2(116.33,103.12)
P1V8_A: length 7.4
  TOP w0.203: C140.1 v5(134.49,88.36) ; v5(127.29,87.56) C134.1 ; C132.1 v5(132.89,81.96) ; C128.1 127.28,81.96 v5(127.29,81.96) ; C138.1 v5(132.89,90.76) ; C136.1 v5(128.89,90.76) ; 126.7,84.12 v5(127.29,84.36)
  BOTTOM w0.254: U1.U10 v5(127.29,84.36) ; U1.J10 v5(134.49,84.36) ; U1.R17 v5(128.89,90.76) ; U1.L7 v5(132.89,81.96) ; U1.L17 v5(132.89,90.76) ; U1.U13 v5(127.29,87.56) ; U1.J14 v5(134.49,88.36)
  BOTTOM w0.279: U1.U7 v5(127.29,81.96)
  vias: v2(119.13,98.3) v2(119.25,100.2) v2(119.25,99.19) v2(120.02,100.76) v2(120.14,104.14) v2(120.14,103.38) v2(120.14,101.98) v6(119.92,99.64)
P1V8_AGND: length 5.1
  TOP w0.254: v2(80.72,106.33) 80.55,106.17 PR368.2
  TOP w0.305: v2(82.78,106.66) 82.53,106.41 PU19.4 80.8,106.41 v2(80.72,106.33)
  BOTTOM w0.305: v2(80.72,106.33) 80.72,106.38 v6(80.19,106.91) 79.84,106.56 PR372.1
P1V8_COMP: length 4.4
  TOP w0.254: PR371.1 77.85,106.6 v1(78.79,106.6) 79.28,107.09 PC547.1 80.07,107.09 80.25,106.91 PU19.3
P1V8_COMP_RC: length 2.9
  TOP w0.254: PR371.2 76.77,108.01 v1(76.99,108.23) 77.34,107.88 PC549.1
P1V8_EN: length 17.9
  TOP w0.254: v2(82.17,109.13) 82.28,109.01 PU19.15
  IN2 w0.254: v2(75.13,105.92) 77.29,105.92 78.43,107.06 78.43,109.27 80.16,111 81.61,111 81.86,110.74 81.86,109.43 v2(82.17,109.13)
  BOTTOM w0.114: PR361.1 77.27,105.68 77.16,105.79 76.02,105.79 75.9,105.92 v2(75.13,105.92)
  BOTTOM w0.127: PR361.1 77.27,105.55 76.96,105.23 PR357.2
  BOTTOM w0.254: PC539.1 81.91,108.16 82.17,108.41 v2(82.17,109.13)
P1V8_FB: length 7.7
  TOP w0.254: PU19.1 81.17,107.91 80.82,108.26 v2(80.74,108.26) 80.72,108.24 80.54,108.24 80.2,107.89 PC547.2 ; PC547.2 PR373.1 80.02,108.87 PR374.1 ; PC547.2 80.03,107.88 PC549.2
  BOTTOM w0.254: v2(80.74,108.26) 80.5,108.51 v6(79,108.51) PR372.2
P1V8_FB_RC: length 3.3
  TOP w0.254: PC555.1 v1(79.09,111.1) 79.48,111.1 80.04,110.53 PR373.2
P1V8_PG: length 152.8
  TOP w0.114: PR363.2 77.57,104.67 v2(77.67,104.78) 79.2,104.78 79.3,104.67 81.33,104.67 81.53,104.87 PU19.6 ; v2(62.77,38.91) 63.96,38.91 v6(64.24,39.19) 64.38,39.34 PR418.1
  IN2 w0.147: v2(77.67,104.78) 77.5,104.78 77.01,104.29 74.22,104.29 73.51,103.58 73.51,102.51 40.97,69.98 40.97,54.71 56.64,39.04 62.64,39.04 v2(62.77,38.91) 66.32,35.36 100.59,35.36 103.51,38.28 103.51,41.86 v2(104.34,42.7)
  BOTTOM w0.114: R211.2 v2(104.34,42.7)
P1V8_RT: length 1.7
  TOP w0.254: PU19.5 81.09,105.91 80.54,105.37 PR368.1
P1V8_SS: length 5.6
  TOP w0.254: v2(80.77,107.45) 80.81,107.41 PU19.2
  BOTTOM w0.254: PR366.2 83.16,105.73 83.44,106.02 83.44,106.86 82.84,107.45 v6(82.67,107.45) 82.15,107.45 81.91,107.22 PR367.1 81,107.22 v2(80.77,107.45)
P1V8_VCC: length 4.3
  TOP w0.254: v2(82.93,104.17) 82.78,104.32 PU19.8
  TOP w0.305: v2(82.93,104.17) 83.18,103.92 PC541.1
  BOTTOM w0.254: v2(82.93,104.17) 83.18,104.17 v6(83.84,104.83) 83.74,104.93 PR366.1
P1V8_VIN: length 4.7
  TOP w0.254: PU19.7 82.28,104.44 v2(82.04,104.2)
  TOP w0.305: PC542.1 81.89,104.05 v2(82.04,104.2)
  BOTTOM w0.305: v6(83.8,102.74) 82.86,102.74 PR370.2 82.04,103.56 v2(82.04,104.2)
P1V8_VSENSE_R: length 27.9
  TOP w0.254: v2(98.38,109.98) 98.4,109.96 PR375.1 ; PR374.2 PC555.2 77.46,109.84 77.09,110.2 v2(77.09,110.24)
  IN2 w0.254: v2(98.38,109.98) 98.38,109.45 97.99,109.07 94.49,109.07 91.04,112.52 78.97,112.52 77.09,110.65 v2(77.09,110.24)
P3V3: length 239.2
  TOP w0.254: v2(300.36,102.51) 300.53,102.34 PR345.2 ; PC1531.1 278.92,113.21 279.5,113.79 302.46,113.79 303,113.25 PR348.2
  TOP w0.305: v2(305.64,60.71) 305.53,60.6 R7.1
  TOP w0.356: U16.5 281.62,70.73 C455.1 ; R142.1 v2(284.81,42.04)
  TOP w0.381: U17.5 281.64,29.06 C456.1 v2(280.89,30.21) ; R4.1 v2(298.51,50.87) ; R143.1 v2(284.81,82.42) ; R194.1 v2(107.07,43.29) ; R110.2 v2(302.85,25.78) ; R209.1 v2(107.77,50.29) ; R3.1 v2(294.59,46.23) ; R204.1 v2(310.72,31.9) ; R153.1 v2(288.04,65.21) ; R163.1 312.64,29.06 v2(313.01,28.7) ; R77.1 v2(295.1,57.99) ; R193.1 315.79,31.9 v2(315.98,32.08) ; v2(71.2,85.85) 71.2,98.04 76.91,103.76 PR363.1 ; R160.1 v2(316.5,30.12) ; R191.1 v2(289.36,24.38) ; U12.8 v2(106.34,42.64) ; R8.1 v2(295.1,60.02) ; R156.1 v2(295.51,69.09) ; R107.1 v2(295.96,68.22) ; R147.1 v2(262.46,24.43) ; C455.1 v2(280.85,70.85) ; R161.1 v2(295.46,24.38) ; v2(290.93,69.72) R159.1
  TOP w0.508: v2(167.34,112.9) 167.34,112.41 R348.1 ; R162.1 296.22,25.27 296.45,25.5 296.45,26.31 v2(296.42,26.31) 296.42,26.54 296.24,26.72 R203.1 ; R109.1 v2(308.07,23.9) ; R210.1 v2(290.15,26.16) 289.91,25.93 R192.1
  TOP w0.762: v2(187.73,115.65) 187.86,115.78 CON1.1 192.05,115.78 192.59,116.31 265.02,116.31 271.35,109.98 276.94,109.98 277.06,109.86
  IN1 w0.762: v2(187.73,115.65) 188.67,114.71 188.67,107.7 184.74,103.76 174.45,103.76 167.34,110.87 v2(167.34,112.9)
  IN2 w0.254: v2(277.92,112.51) 279.21,113.79 296.97,113.79 300.92,109.84 300.92,103.07 v2(300.36,102.51)
  BOTTOM w0.254: PR420.1 v2(64.69,50.42) ; PR336.1 302.03,102.67 v2(302.09,102.73)
  BOTTOM w0.381: R296.1 v2(105.36,42.65) ; C450.1 106.38,42.68 v2(106.34,42.64)
  vias: v2(100.92,52.32) v2(100.92,51.18) v2(100.92,50.04) v2(100.92,48.77) v2(276.74,106.46) v2(276.74,104.23) v2(276.74,101.99) v2(277.43,106.46) v2(277.43,104.23) v2(277.43,101.99) v2(277.92,111.82) v2(277.92,111.06) v2(277.92,110.3) v2(277.92,109.56) v2(277.92,108.82) v2(285.65,32.36) v2(285.83,72.9) v2(287.35,31.88) v2(287.48,72.52) v2(288.24,31.88) v2(288.49,72.52) v2(307.68,54.05) v2(307.68,53.29) v6(276.89,100.99)
P3V3_AGND: length 5.6
  TOP w0.254: PR344.1 299.73,105.17 299.63,105.27 v2(299.62,105.27)
  BOTTOM w0.254: PR339.2 301.91,103.81 301.65,104.06 301.07,104.06 299.87,105.27 v2(299.62,105.27) 299.36,105.27 298.88,105.75 PU17.4
  vias: v1(297.11,106.07) v2(296.93,105.74)
P3V3_BUF_VDDA:
  vias: v2(294.98,56.08)
P3V3_BUF_VDDR: length 2.1
  TOP w0.178: 300.51,56.32 U9.5 300.51,55.07 300.29,54.85 C227.1
P3V3_CLK_BUF_VDD: length 24.6
  TOP w0.178: C218.1 300.68,62.49 300.91,62.26 U9.25 300.91,61.07 ; 298.34,60.5 U9.31 297.67,60.5 297.41,60.76 296.8,60.76 C221.1 ; C217.1 303.77,57.3 U9.12 303.09,57.3 ; 303.09,58.9 U9.16 304.27,58.9 304.5,59.13 C258.1 ; C216.1 296.62,58.9 U9.35 298.34,58.9 ; C220.1 296.85,57.3 U9.39 298.34,57.3 ; C257.1 304.45,61.39 303.56,60.5 U9.20 303.09,60.5 ; 299.31,61.07 U9.29 299.31,61.58 298.42,62.47 C219.1 ; 302.51,61.07 U9.21 302.51,61.76 C222.1
  TOP w0.381: v2(297.76,62.72) C219.1 ; C220.1 296.77,56.72 v2(297.13,56.72) ; C258.1 304.73,58.89 v2(305.11,58.52) ; C216.1 296.9,59.38 v2(297.13,59.38) ; R1.1 v2(296.85,52.89) ; v2(301.29,63.1) 300.92,62.72 C218.1 ; R91.1 v2(301.34,51.11) ; C222.1 303.49,62.47 v2(303.86,62.84) ; C257.1 304.73,60.93 v2(304.94,60.72) ; v2(297.13,61.29) 296.77,61.29 C221.1
  TOP w0.457: R92.1 v2(294.98,54.05)
  vias: v2(304.5,52.53) v2(305.26,52.53)
P3V3_COMP: length 5.4
  BOTTOM w0.254: PU17.3 298.99,106.25 299.44,105.79 299.75,105.79 299.99,106.03 PC516.1 300.3,105.7 v6(301.33,104.67) 301.33,105.75 PR342.1
P3V3_COMP_RC: length 3.7
  BOTTOM w0.254: PR342.2 302.46,105.83 v6(303.05,105.23) 303.05,106.56 302.8,106.82 PC518.1
P3V3_EN: length 9.4
  TOP w0.254: v2(299.47,110.07) 299.47,110.4 299.94,110.87 PR332.2
  BOTTOM w0.127: PC506.1 299.91,112.73 300.21,113.03 v6(300.46,113.03)
  BOTTOM w0.203: v2(299.47,110.07) 299.47,109.33 298.55,108.41 297.26,108.41 296.91,108.06 PU17.15
  BOTTOM w0.254: v2(299.47,110.07) 299.47,110.25 299.9,110.68 PR333.1 299.9,111.74 PC506.1
P3V3_FB: length 6.9
  TOP w0.254: v4(299.6,107.31) 300.31,106.61 PR344.2
  BOTTOM w0.254: PR347.1 300.32,107.81 PR346.1 PC516.2 ; PU17.1 299.53,107.25 v4(299.6,107.31) 299.78,107.31 300.26,106.83 PC516.2 ; PC518.2 301.25,106.83 PC516.2
P3V3_FB_RC: length 1.9
  BOTTOM w0.254: PC527.1 300.78,109.25 300.26,109.25 v4(300.24,109.22) 300.24,108.65 PR346.2
P3V3_MB:
  vias: v2(288.37,9.27) v2(288.37,8.51) v2(288.37,7.77) v2(288.37,7.11) v2(289.03,9.27) v2(289.03,8.51) v2(289.03,7.77) v2(289.03,7.11) v3(289.36,10.57)
P3V3_PG: length 460.9
  TOP w0.114: R298.1 296.85,52.07 286.41,52.07 v2(285.85,51.51)
  IN2 w0.147: v2(75.13,103.76) 75.13,103.46 41.45,69.78 41.45,54.91 47.51,48.84 59.72,48.84 60.94,47.62 60.94,42.69 67.28,36.35 99.93,36.35 102.6,39.02 102.6,45.52 104.52,47.45 107.44,47.45 108.32,48.32 130.95,48.32 132.38,49.75 179.97,49.75 182.76,46.96 204.78,46.96 206.33,45.41 206.33,33.41 217.7,22.03 275.56,22.03 278.73,25.21 278.73,28.21 280.09,29.57 281.27,29.57 284.43,32.72 284.43,34.02 283.57,34.87 283.41,34.87 281.89,36.4 281.54,36.4 280.9,37.03 280.9,38.15 281.64,38.89 281.64,41.21 280.36,42.49 280.36,46.02 v2(285.85,51.51) 285.85,60.1 280.09,65.86 280.09,73 279.83,73.25 279.83,74.11 280.02,74.56 280.59,75.13 280.9,75.88 280.9,78.74 281.76,79.6 281.76,84.18 282.3,84.71 282.3,87.48 v2(281.31,88.47)
  BOTTOM w0.114: PR336.2 301.23,97.75 298.6,95.12 287.96,95.12 v2(281.31,88.47)
  BOTTOM w0.127: PR357.1 75.45,103.76 v2(75.13,103.76)
  BOTTOM w0.254: PU17.7 298.47,104.25 298.83,103.89 298.83,102.49 299.44,101.88 PR336.2
P3V3_RT: length 3.6
  BOTTOM w0.254: PU17.5 298.83,105.25 299.78,104.3 v6(299.96,104.3) 300.13,104.3 300.92,103.5 PR339.1
P3V3_SENSE_R: length 4.2
  TOP w0.254: PR348.1 v2(303,110.11)
  BOTTOM w0.254: v2(303,110.11) 302.57,110.11 302.05,109.59 PC527.2 PR347.2
P3V3_STBY_MB: length 160.1
  TOP w0.254: U10.1 198.48,81.71 v2(198.17,82.02) ; C352.1 281.4,20.16 U8.5 ; 263.22,27.58 U3.8
  TOP w0.305: U2.24 308.04,35.85 308.47,36.28 C223.1
  TOP w0.356: U19.5 285.82,86.37 C460.1 ; U20.5 285.82,45.86 C461.1
  TOP w0.381: R252.1 v2(287.86,84.71) ; R100.1 v2(301.96,46.89) ; R261.1 v2(287.86,44.09) ; v2(305.94,27.79) R186.1 R185.1 ; R257.1 v2(291.54,70.23) ; v2(307.67,46.89) R95.1 ; R258.1 R259.1 v2(289.51,70.23) ; R285.1 v2(311.91,46.25) ; R106.1 v2(303.86,27.81) ; 263.22,27.58 263.22,26.98 263.48,26.72 C179.1 C178.1 v2(268.64,26) ; R104.1 v2(301.83,27.79) ; R99.1 R98.1 v2(304.24,46.89) ; C223.1 v2(309.12,35.66) ; R78.1 v2(307.67,44.63) ; C352.1 v2(281.49,20.95) ; R81.1 v2(308.81,46.89) ; R101.1 300.69,46.37 v2(300.05,46.37) 299.29,46.37 R102.1 ; R281.1 v2(315.85,46.25) ; v2(315.91,33.67) C452.1 U7.8 ; R283.1 v2(313.89,46.91) ; R83.1 v2(309.96,46.89) ; R145.1 v2(299.54,26.01) ; 209.73,79.35 R141.1 R137.1 ; 209.73,79.35 209.75,79.35 211.86,81.46 211.86,83.92 219.33,91.39 282.2,91.39 v2(285.7,87.88) ; 209.73,79.35 v2(209.75,79.38) ; R97.1 v2(305.39,46.86) ; C460.1 v2(285.83,87) ; R79.1 v2(306.96,27.79) ; R264.1 R263.1 v2(290.4,29.49) ; R96.1 v2(306.53,46.86) ; R105.1 v2(302.85,27.81) ; R88.1 v2(308.99,31.98) ; R262.1 v2(291.42,29.49) ; R144.1 v2(297.85,26.65) ; v2(300.15,27.89) R103.1 ; R87.1 v2(307.98,31.98) ; R293.1 v2(313.89,30.45) ; R152.1 v2(263,12.34)
  TOP w0.457: v2(285.83,46.53) C461.1
  IN2 w0.381: v2(198.17,82.02) 198.17,82.78 198.83,83.44 206.83,83.44 207.72,82.55 207.72,81.41 v2(209.75,79.38)
  BOTTOM w0.254: C259.1 306.49,76.69 306.49,77.51 306.23,77.76 U4.1
  BOTTOM w0.381: C265.1 198.17,82.42 v2(198.17,82.02) ; R301.1 v2(314.4,80.14) ; v2(305.41,76.35) C259.1 ; R302.1 v2(309.07,81.15)
  BOTTOM w0.762: J5.B10 286.83,6.02 287.08,6.27 287.08,6.29 287.13,6.34 v2(287.13,11.13)
  vias: v2(286.39,11.91) v2(286.84,42.04)
P3V3_VCC: length 10.2
  IN2 w0.254: v2(299.63,102.7) 299.28,103.05 297.26,103.05 v4(296.3,102.08)
  BOTTOM w0.254: v4(296.3,102.08) 296.3,102.57 296.41,102.68 PU17.10 ; PU17.6 298.71,104.75 299.32,104.14 299.32,103.01 v2(299.63,102.7)
  BOTTOM w0.381: PC508.2 297.03,101.22 296.3,101.96 v4(296.3,102.08)
P3V3_VIN: length 5.3
  TOP w0.381: v4(297.59,102.08) 296.86,101.34 PR341.2
  BOTTOM w0.254: v4(297.59,102.08) 296.91,102.77 PU17.9
  BOTTOM w0.381: v4(297.59,102.08) 297.59,101.66 298.33,100.92 PC510.1
P3V3_VREF: length 2.4
  TOP w0.254: PC509.1 299.24,106.05 v2(299.57,106.38)
  BOTTOM w0.254: PU17.2 299.21,106.75 v2(299.57,106.38)
P3V3_VSNS: length 6.3
  TOP w0.254: PR345.1 299.31,101.85 v2(298.52,101.85) 298.76,102.09 298.76,102.62 v1(298.74,102.64) 297.69,103.68 PR343.2
  BOTTOM w0.254: PU17.8 297.41,103.21 298.52,102.1 v2(298.52,101.85)
P12V: length 0.9
  TOP w0.254: v2(301.48,111.67) PR332.1
  vias: v2(1.91,93.78) v2(2.03,92.76) v2(1.96,88.9) v2(2.08,87.88) v2(3.48,88.72) v2(3.61,87.71) v2(3.66,96.24) v2(3.79,95.22) v2(4.42,98.91) v2(4.55,97.89) v2(5.21,88.87) v2(5.34,87.86) v2(6.48,89.53) v2(6.61,88.52) v2(7.19,104.65) v2(7.32,91.95) v2(7.44,101.98) v2(7.44,95.12) v2(7.57,104.01) v2(7.57,100.58) v2(7.57,99.06) v2(7.57,97.92) v2(7.57,94.11) v2(7.57,92.96) v2(7.7,96.01) v2(7.82,103.12) v2(8.21,97.16) v2(8.59,102.62) v2(8.59,99.95) v2(8.71,93.85) v2(9.35,103.12) v2(9.48,96.9) v2(9.6,93.47) v2(9.73,102.49) v2(9.86,100.33) v2(9.86,99.57) v2(9.98,94.49) v2(10.11,96.01) v2(10.24,105.16) v2(10.24,104.27) v2(10.24,103.38) v2(10.24,101.73) v2(10.24,97.92) v2(10.24,92.58) v2(13.03,100.2) v2(13.03,99.31) v2(13.03,94.36) v2(13.03,93.47) v2(83.19,39.88) v2(83.16,39.14) v2(83.19,38.33) v2(83.77,39.5) v2(83.8,38.68) v2(90.19,109.84) v2(90.19,109.18) v2(90.19,108.52) v2(282.56,112.27) v2(282.56,111.51) v2(283.14,112.57) v2(283.12,111.86) v2(283.12,111.18) v2(293.42,32) v2(293.57,72.52) v2(294.06,31.95) v2(294.34,41.83) v2(294.97,41.81) v2(295.56,83.82) v2(295.61,83.16) v2(295.86,33.53) v2(295.86,32.77)
P12V_MB: length 3.3
  BOTTOM w0.508: 295.05,6.48 295.83,5.7 J5.B1
  vias: v2(293.14,7.87) v2(293.14,7.11) v2(293.8,8.61) v2(293.8,7.87) v2(293.8,7.11) v2(294.46,8.61) v2(294.46,7.87) v2(294.46,7.11)
P12V_PSU:
  vias: v2(12.4,86.74) v2(13.03,87.25) v2(13.03,86.36)
85OHM_BOT_5INCH_DN: length 127
  BOTTOM w0.135: U41.2 -13.97,200.55 -13.97,203.4 -13.38,204.24 -12.51,204.4 -9.32,203.83 -9.2,203.92 -9.09,204.56 -9.21,204.73 -16.35,205.99 -16.68,206.45 -16.55,207.18 -16.12,207.47 -7.86,206.02 -7.72,206.12 -7.61,206.73 -7.66,206.81 -7.71,206.87 -7.73,206.91 -7.78,206.92 -7.89,206.94 -17.4,208.62 -17.72,209.08 -17.6,209.8 -17.17,210.1 -7.87,208.46 -7.7,208.58 -7.61,209.14 -7.76,209.35 -17.38,211.05 -17.65,211.44 -17.51,212.26 -17.11,212.53 -8.7,211.05 -8.53,211.17 -8.43,211.72 -8.58,211.94 -17.48,213.51 -17.75,213.89 -17.6,214.73 -17.21,214.99 -7.9,213.35 -7.68,213.51 -7.6,213.96 -7.8,214.24 -17.63,215.98 -17.91,216.37 -17.77,217.15 -17.34,217.46 -7.72,215.76 -7.51,215.91 -7.42,216.43 -7.57,216.64 -14.93,217.94 -15.15,218.26 -14.93,219.5 -14.93,221.74 U39.1
85OHM_BOT_5INCH_DP: length 127
  BOTTOM w0.135: U41.1 -13.67,200.56 -13.67,203.31 -13.21,203.96 -12.51,204.09 -9.25,203.51 -9.02,203.67 -8.92,203.74 -8.76,204.63 -9.03,205 -16.18,206.26 -16.35,206.52 -16.27,207 -16.05,207.15 -7.79,205.7 -7.61,205.82 -7.44,205.94 -7.29,206.8 -7.41,206.98 -7.48,207.09 -7.56,207.19 -17.23,208.9 -17.4,209.15 -17.32,209.62 -17.09,209.78 -7.8,208.14 -7.42,208.4 -7.28,209.21 -7.58,209.63 -17.2,211.33 -17.33,211.51 -17.23,212.08 -17.04,212.21 -8.63,210.73 -8.25,210.99 -8.11,211.79 -8.4,212.22 -10.18,212.53 -17.31,213.79 -17.43,213.96 -17.32,214.54 -17.14,214.67 -7.83,213.03 -7.41,213.33 -7.28,214.03 -7.62,214.52 -17.45,216.26 -17.59,216.44 -17.49,216.97 -17.27,217.13 -7.65,215.44 -7.23,215.73 -7.1,216.5 -7.39,216.92 -14.75,218.22 -14.83,218.33 -14.63,219.48 -14.63,221.75 U39.2
85OHM_BOT_10INCH_DN: length 254
  BOTTOM w0.135: U43.1 -14.63,9.78 -14.63,12.53 -14.17,13.19 -13.48,13.31 -10.22,12.73 -9.99,12.89 -9.99,12.89 -9.88,12.97 -9.73,13.85 -9.99,14.22 -17.14,15.49 -17.32,15.74 -17.23,16.22 -17.01,16.37 -8.76,14.92 -8.4,15.16 -8.25,16.05 -8.49,16.4 -17.42,17.98 -17.54,18.14 -17.43,18.73 -17.26,18.86 -8.77,17.36 -8.39,17.63 -8.25,18.43 -8.54,18.85 -17.24,20.39 -17.38,20.58 -17.28,21.15 -17.1,21.27 -8.71,19.79 -8.29,20.09 -8.17,20.78 -8.42,21.29 -17.55,22.9 -17.71,23.13 -17.62,23.66 -17.45,23.77 -8.44,22.19 -8.04,22.46 -7.89,23.3 -8.15,23.67 -17.49,25.31 -17.64,25.51 -17.56,26.04 -17.37,26.2 -8.54,24.65 -8.12,24.94 -7.98,25.76 -8.23,26.12 -17.39,27.75 -17.52,27.94 -17.42,28.51 -17.26,28.63 -8.25,27.04 -7.87,27.3 -7.73,28.12 -8.01,28.52 -17.56,30.21 -17.67,30.38 -17.57,30.96 -17.39,31.09 -8.22,29.47 -7.82,29.75 -7.68,30.55 -7.97,30.96 -17.49,32.64 -17.6,32.79 -17.49,33.4 -17.32,33.52 -8.18,31.91 -7.79,32.18 -7.65,33 -7.93,33.39 -17.43,35.07 -17.58,35.28 -17.48,35.86 -17.33,35.96 -8.27,34.36 -7.79,34.69 -7.67,35.43 -7.96,35.84 -17.43,37.51 -17.55,37.69 -17.45,38.27 -17.26,38.39 -7.96,36.75 -7.53,37.05 -7.41,37.76 -7.75,38.25 -17.58,39.98 -17.71,40.17 -17.62,40.7 -17.39,40.86 -7.78,39.16 -7.36,39.46 -7.22,40.22 -7.52,40.65 -14.84,41.94 -14.95,42.09 -14.75,43.2 -14.75,45.47 U45.2
